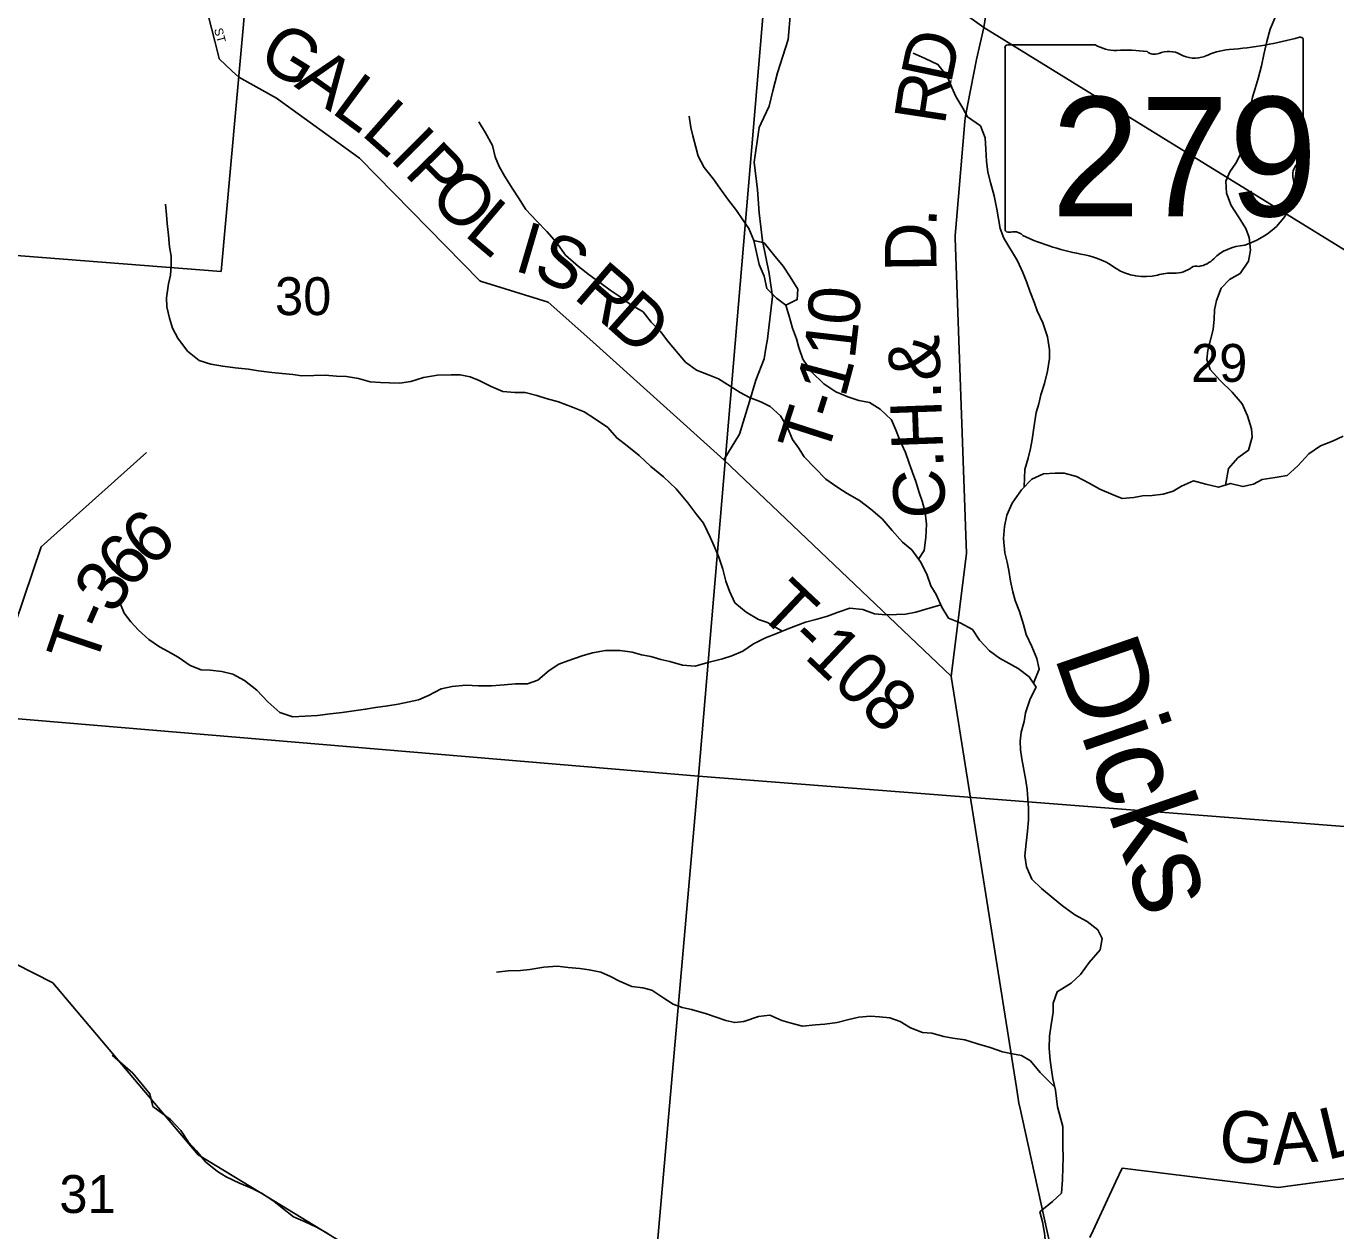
# Model space of a CAD drawing. Extents: x 1715311 to 2083412, y 146837 to 553079.
# Drawn here: x 1950183 to 1957824, y 317977 to 325005 of the extents above; entities that cross this region are included whole.
import ezdxf

# ---------------------------------------------------------------- set-up
doc = ezdxf.new("R2010")
doc.units = 0
for name, color, linetype in [('GM_X_City_Street', 7, 'Continuous'), ('GM_X_City_Street_Text', 7, 'Continuous'), ('GM_X_Corporation', 7, 'Continuous'), ('GM_X_County_Road', 7, 'Continuous'), ('GM_X_County_Road_Text', 7, 'Continuous'), ('GM_X_Minor_Lake', 7, 'Continuous'), ('GM_X_Minor_River', 7, 'Continuous'), ('GM_X_Minor_River_Text', 7, 'Continuous'), ('GM_X_Section', 7, 'Continuous'), ('GM_X_Section_Text', 7, 'Continuous'), ('GM_X_State_Location', 7, 'Continuous'), ('GM_X_State_Route', 7, 'Continuous'), ('GM_X_State_Shield', 7, 'Continuous'), ('GM_X_Township_Road', 7, 'Continuous'), ('GM_X_Township_Road_Text', 7, 'Continuous'), ('GM_X_Township_ROW', 7, 'Continuous')]:
    doc.layers.add(name, color=color, linetype=linetype)

msp = doc.modelspace()

# ---------------------------------------------------------------- linework, layer by layer
at = {"layer": 'GM_X_City_Street'}
msp.add_lwpolyline([(1951423.1, 324707.2), (1951385.1, 324743.2), (1951309.1, 324815.3), (1951309, 324815.4), (1951283.4, 324916.9), (1951245.1, 325069.3), (1951245.1, 325069.4)], dxfattribs=at)
at = {"layer": 'GM_X_Corporation'}
msp.add_lwpolyline([(1951553, 326137.7), (1951320.1, 323573.7), (1948435.1, 323799.8), (1948400, 323332.9), (1945758.3, 323632.3), (1946231.5, 329032.2)], dxfattribs=at)
at = {"layer": 'GM_X_County_Road'}
for points in [[(1955769.4, 324997.5), (1955798.2, 325171.4), (1955929.3, 325842), (1956302.2, 327750.6), (1956335.4, 327888.1)], [(1956223.5, 317578.5), (1956214.1, 317630.7), (1956206.7, 317671.7), (1956192.9, 317733.6), (1955977.5, 318708.8), (1955977.1, 318709.8), (1955960.8, 318812.4), (1955581.8, 321199.9), (1955579.4, 321213.7), (1955590.7, 321304.2), (1955668.8, 321930), (1955668.8, 321930.8), (1955665.1, 322035), (1955603.4, 323768.3), (1955602.7, 323782.8), (1955610.4, 323873), (1955659.2, 324449.1), (1955660.8, 324468.2), (1955677.3, 324552.4), (1955727.7, 324810.4), (1955769.4, 324997.5)]]:
    msp.add_lwpolyline(points, dxfattribs=at)
at = {"layer": 'GM_X_Minor_Lake'}
for points in [[(1954428.4, 323754.4), (1954459.7, 323614.2), (1954489.3, 323546), (1954505, 323473.8), (1954560.6, 323417.6), (1954614.3, 323377.3)], [(1954614.3, 323377.3), (1954682.1, 323410.1), (1954686, 323470.1), (1954640.1, 323542.2), (1954600.2, 323604.2), (1954542.4, 323672.2), (1954488.5, 323740.2), (1954428.4, 323754.4)]]:
    msp.add_lwpolyline(points, dxfattribs=at)
at = {"layer": 'GM_X_Minor_River'}
for points in [[(1957179.3, 322327.4), (1957198.3, 322425.1), (1957252.5, 322486.9), (1957314.5, 322530.6), (1957336.8, 322606.6), (1957331, 322656.6), (1957309.4, 322730.8), (1957277.8, 322801), (1957218.2, 322869.3), (1957148.7, 322937.7), (1957091.1, 323002), (1957071.4, 323060.1), (1957077.6, 323114.1), (1957091.8, 323174.1), (1957108.1, 323236.1), (1957114.3, 323296.1), (1957116.5, 323350.1), (1957126.8, 323404.1), (1957155, 323476), (1957203.1, 323527.9), (1957265.1, 323561.6), (1957315.3, 323633.4), (1957325.6, 323697.4), (1957317.9, 323771.5), (1957298.2, 323823.6), (1957256.6, 323891.9), (1957213, 323958.1), (1957185.3, 324030.3), (1957181.7, 324100.4), (1957205.8, 324154.3), (1957240, 324206.2), (1957274.2, 324270.1), (1957284.4, 324338.1), (1957300.8, 324418.1), (1957313, 324480.1), (1957325.2, 324536), (1957337.4, 324590), (1957353.6, 324642), (1957371.8, 324700), (1957390.1, 324773.9), (1957404.4, 324839.9), (1957420.7, 324915.9), (1957440.9, 324987.9), (1957473.2, 325065.8)], [(1956006.5, 322316.8), (1956009, 322418.4), (1956029.2, 322484.3), (1956043.4, 322540.3), (1956051.6, 322594.3), (1956061.9, 322662.3), (1956076.3, 322750.3), (1956090.5, 322802.3), (1956102.7, 322854.3), (1956124.9, 322920.2), (1956141.2, 322992.2), (1956153.5, 323066.2), (1956153.7, 323116.3), (1956142, 323192.4), (1956114.4, 323274.5), (1956080.8, 323344.8), (1956063.1, 323394.9), (1956039.4, 323459), (1956021.7, 323509.1), (1955998, 323567.3), (1955966.4, 323635.5), (1955887.1, 323767.9), (1955865.4, 323824.1), (1955855.7, 323880.1), (1955845.9, 323938.2), (1955830.3, 324014.4), (1955808.7, 324092.5), (1955793, 324152.6), (1955785.3, 324216.7), (1955781.6, 324286.8), (1955777.9, 324352.8), (1955750.3, 324423), (1955674.7, 324475.4), (1955646.9, 324525.6), (1955607.3, 324593.8), (1955583.6, 324647.9), (1955556, 324714.1), (1955502.4, 324780.4), (1955428.7, 324816.7), (1955359, 324847.1)], [(1952904.3, 324309.5), (1952862.7, 324381.7), (1952825.1, 324445.9)], [(1955388.8, 321896.1), (1955422.3, 321946.6), (1955432.6, 322022.7), (1955434.9, 322098.7), (1955427.2, 322168.8), (1955411.5, 322232.9), (1955393.8, 322285), (1955374.1, 322349.2), (1955354.4, 322401.3), (1955332.7, 322461.4), (1955313, 322517.6), (1955279.4, 322589.8), (1955255.7, 322653.9), (1955232, 322708.1), (1955166.4, 322770.4), (1955102.7, 322808.7), (1955040.9, 322821), (1954977.2, 322843.3), (1954907.4, 322871.6), (1954837.8, 322918), (1954764.3, 322988.3), (1954714.7, 323062.6), (1954691.1, 323130.8), (1954677.3, 323180.9), (1954653.6, 323243), (1954634, 323313.2), (1954614.3, 323377.3), (1954560.6, 323417.6), (1954505, 323473.8), (1954489.3, 323546), (1954459.7, 323614.2), (1954428.4, 323754.4), (1954398.7, 323824.6), (1954365, 323874.8), (1954327.3, 323929), (1954275.8, 323997.2), (1954230.1, 324059.5), (1954192.5, 324111.7), (1954138.9, 324180), (1954103.2, 324246.2), (1954089.5, 324298.3), (1954071.8, 324364.4), (1954060.1, 324414.5), (1954050.4, 324480.6)], [(1956200.5, 318700.1), (1956188.9, 318796.9), (1956173.2, 318863), (1956165.4, 318917.1), (1956157.7, 318973.1), (1956152, 319041.2), (1956154.3, 319113.3), (1956162.6, 319179.3), (1956174.9, 319253.3), (1956175.1, 319305.3), (1956197.3, 319371.3), (1956279.4, 319420.9), (1956333.5, 319472.7), (1956385.6, 319542.6), (1956449.8, 319616.3), (1956460.1, 319682.3), (1956436.4, 319732.5), (1956372.7, 319780.8), (1956301.1, 319821.1), (1956229.4, 319873.5), (1956175.7, 319917.8), (1956106.1, 319974.1), (1956050.5, 320028.4), (1956018.9, 320100.6), (1956009.2, 320164.7), (1956017.5, 320238.7), (1956025.8, 320308.7), (1956030.1, 320374.8), (1956030.4, 320444.8), (1956026.6, 320496.9), (1956022.8, 320550.9), (1956015.1, 320605), (1956001.4, 320677.1), (1955991.7, 320731.2), (1955983.9, 320783.3), (1955982.2, 320833.3), (1955988.4, 320885.3), (1956006.6, 320949.3), (1956012.8, 320999.3), (1956041.1, 321081.2), (1956075.3, 321149.1), (1956035.7, 321209.4), (1955970, 321257.7), (1955918.3, 321286), (1955862.5, 321318.2), (1955802.9, 321360.5), (1955745.2, 321422.8), (1955703.6, 321485.1), (1955631.9, 321523.4), (1955564.2, 321551.7), (1955524.6, 321616), (1955493, 321690.1), (1955461.3, 321740.3), (1955437.6, 321808.5), (1955400, 321880.7), (1955350.4, 321949), (1955296.7, 321995.2), (1955235.2, 322063.6), (1955177.6, 322129.9), (1955112, 322186.2), (1955044.4, 322238.6), (1954972.7, 322278.9), (1954919, 322313.2), (1954849.3, 322361.5), (1954783.8, 322427.8), (1954722.2, 322492.2), (1954688.5, 322544.4), (1954654.8, 322594.5), (1954625.2, 322662.7), (1954583.6, 322731), (1954523.9, 322785.3), (1954470.2, 322813.5), (1954402.4, 322837.8), (1954348.7, 322868.1), (1954275.1, 322914.5), (1954223.3, 322946.7), (1954163.6, 322971), (1954093.8, 322997.3), (1954030.2, 323045.6), (1953986.5, 323095.8), (1953925, 323168.2), (1953885.3, 323222.4), (1953829.7, 323278.7), (1953782, 323338.9), (1953708.4, 323381.3), (1953642.8, 323429.6), (1953591, 323463.9), (1953537.3, 323504.1), (1953467.7, 323554.5), (1953406.1, 323602.8), (1953330.5, 323669.1), (1953277, 323743.4), (1953221.4, 323807.7), (1953159.8, 323870), (1953098.2, 323936.3), (1953054.6, 324002.6), (1953022.9, 324054.8), (1952975.3, 324127), (1952943.7, 324187.2), (1952920, 324243.3), (1952904.3, 324309.5)], [(1954593.8, 321476), (1954508.5, 321526.4), (1954456.7, 321542.6), (1954383.1, 321587), (1954317.4, 321641.3), (1954285.8, 321709.5), (1954266.1, 321767.6), (1954248.4, 321837.8), (1954224.8, 321907.9), (1954197.1, 321972.1), (1954173.4, 322024.2), (1954133.9, 322104.5), (1954096.2, 322154.7), (1954042.6, 322225), (1953975.1, 322305.3), (1953901.6, 322375.7), (1953828, 322436.1), (1953760.5, 322500.4), (1953688.9, 322556.8), (1953629.2, 322603), (1953577.6, 322663.3), (1953498, 322715.7), (1953438.3, 322754), (1953370.6, 322782.3), (1953288.9, 322812.7), (1953217.2, 322833), (1953163.4, 322849.3), (1953093.6, 322867.6), (1953033.7, 322867.8), (1952963.9, 322874.2), (1952896.2, 322902.5), (1952826.5, 322936.8), (1952772.7, 322959), (1952714.9, 322971.3), (1952663.1, 322971.5), (1952583.2, 322967.9), (1952501.4, 322956.2), (1952427.4, 322932.5), (1952363.5, 322922.8), (1952303.7, 322925), (1952249.8, 322925.3), (1952190, 322929.5), (1952122.2, 322949.8), (1952052.4, 322960.2), (1951994.6, 322962.4), (1951926.8, 322968.7), (1951860.9, 322967), (1951791.1, 322965.3), (1951739.3, 322973.5), (1951677.4, 322977.8), (1951615.6, 322984), (1951537.8, 322994.4), (1951480, 323004.6), (1951402.2, 323011), (1951330.4, 323021.3), (1951260.6, 323033.6), (1951192.9, 323053.9), (1951125.3, 323108.2), (1951067.8, 323184.5), (1951036.1, 323242.7), (1951020.4, 323300.8), (1951004.7, 323367), (1951002.9, 323421), (1951013.3, 323501), (1951025.5, 323553), (1951029.7, 323611), (1951029.9, 323663.1), (1951020.2, 323717.1), (1951014.5, 323785.2), (1951006.8, 323853.3), (1951001, 323903.4), (1950995.3, 323967.4)], [(1956060.6, 321171.5), (1956093.7, 321253.1), (1956080, 321315.2), (1956050.4, 321385.4), (1956016.8, 321455.6), (1956001.1, 321513.8), (1955977.5, 321589.9), (1955953.8, 321654.1), (1955940, 321704.2), (1955926.3, 321766.3), (1955916.6, 321828.4), (1955906.9, 321878.5), (1955893.1, 321932.5), (1955885.5, 322016.6), (1955891.8, 322086.7), (1955904.1, 322152.7), (1955936.3, 322222.6), (1955990.5, 322300.4), (1956050.6, 322362.2), (1956118.6, 322393.9), (1956186.5, 322397.6), (1956238.4, 322397.3), (1956310.1, 322377), (1956385.8, 322338.6), (1956447.5, 322304.3), (1956525.2, 322270), (1956577, 322249.7), (1956644.8, 322255.4), (1956696.8, 322265.2), (1956752.7, 322266.9), (1956816.5, 322274.7), (1956874.5, 322292.4), (1956924.5, 322322.2), (1956994.5, 322351.9), (1957066.2, 322333.6), (1957140, 322315.2), (1957209.9, 322336.9), (1957281.7, 322318.6), (1957343.6, 322332.3), (1957393.6, 322360.1), (1957469.5, 322371.8), (1957539.4, 322383.5), (1957601.5, 322439.2), (1957665.7, 322509), (1957733.7, 322556.7), (1957803.7, 322584.5), (1957867.7, 322612.2)], [(1955519.4, 321628.1), (1955426.7, 321602.4), (1955372.8, 321586.6), (1955312.9, 321574.9), (1955261, 321573.1), (1955199.1, 321571.4), (1955133.3, 321575.7), (1955063.6, 321602), (1954987.8, 321610.3), (1954919.8, 321586.6), (1954857.9, 321562.9), (1954789.9, 321543.2), (1954730, 321527.4), (1954674, 321505.7), (1954622.1, 321487.9), (1954556.1, 321460.1), (1954496.1, 321436.4), (1954426.1, 321400.7), (1954364.1, 321358.9), (1954300.1, 321331.2), (1954246.2, 321313.4), (1954160.3, 321291.8), (1954086.4, 321272.1), (1954012.6, 321276.4), (1953938.8, 321298.7), (1953885, 321311), (1953827.2, 321327.2), (1953773.4, 321337.5), (1953719.6, 321353.7), (1953647.8, 321362.1), (1953564, 321362.4), (1953488.1, 321348.8), (1953426.1, 321331), (1953344.2, 321301.3), (1953290.3, 321283.6), (1953234.2, 321245.8), (1953168.1, 321190), (1953108.2, 321168.3), (1953038.3, 321168.6), (1952972.5, 321162.9), (1952898.6, 321157.2), (1952822.8, 321155.5), (1952749, 321159.8), (1952669.1, 321152.2), (1952605.2, 321138.4), (1952531.2, 321100.7), (1952471.3, 321075), (1952417.3, 321063.2), (1952353.4, 321049.5), (1952293.5, 321039.7), (1952221.7, 321030), (1952163.8, 321020.2), (1952081.9, 321008.6), (1952026, 321000.8), (1951956.1, 320993.1), (1951882.3, 320983.4), (1951738.6, 320976), (1951662.9, 321000.4), (1951593.3, 321062.7), (1951529.7, 321131), (1951456.2, 321187.4), (1951388.5, 321223.7), (1951324.7, 321240), (1951256.9, 321248.3), (1951205, 321250.5), (1951139.3, 321274.8), (1951069.7, 321323.1), (1951012, 321357.4), (1950960.2, 321383.7), (1950898.5, 321426), (1950838.9, 321480.3), (1950793.2, 321530.5), (1950755.6, 321580.7), (1950733.8, 321632.8)], [(1956184.6, 318814.7), (1956099.5, 318901.4), (1956041.9, 318967.7), (1955990.2, 318999.9), (1955938.3, 319010.2), (1955878.5, 319020.4), (1955806.8, 319046.8), (1955733.1, 319067.1), (1955659.3, 319091.5), (1955589.5, 319101.8), (1955537.7, 319110), (1955467.9, 319130.3), (1955412.1, 319134.6), (1955342.3, 319160.9), (1955282.6, 319197.2), (1955222.9, 319219.5), (1955161, 319225.8), (1955109.2, 319230), (1955041.3, 319224.3), (1954983.4, 319210.6), (1954915.5, 319192.9), (1954843.6, 319183.2), (1954787.7, 319179.4), (1954711.8, 319171.7), (1954646, 319188), (1954592.2, 319204.3), (1954522.5, 319234.6), (1954456.6, 319226.9), (1954370.7, 319197.3), (1954316.8, 319191.5), (1954265, 319203.7), (1954151.4, 319242.3), (1954065.7, 319268.7), (1954009.9, 319278.9), (1953958.1, 319299.2), (1953904.4, 319333.4), (1953832.7, 319381.8), (1953780.9, 319394), (1953717.1, 319402.3), (1953645.4, 319432.6), (1953591.7, 319460.9), (1953535.9, 319485.2), (1953468.1, 319499.5), (1953414.3, 319507.7), (1953344.4, 319514), (1953282.6, 319520.3), (1953202.8, 319514.6), (1953120.9, 319501), (1953067, 319495.2), (1952995.2, 319493.5), (1952927.3, 319485.8)], [(1950922.8, 318703.1), (1950905, 318776), (1950859.4, 318830.2), (1950805.8, 318896.5), (1950746.2, 318948.8), (1950684.5, 319001.1)], [(1951942.9, 317961.1), (1951876.8, 317999.1), (1951810.8, 318029.1), (1951742.7, 318059), (1951678.6, 318109.1), (1951628.6, 318149.1), (1951556.5, 318197.1), (1951502.5, 318223.1), (1951428.4, 318255.1), (1951350.3, 318291.1), (1951300.3, 318323.1), (1951230.2, 318379.1), (1951176.1, 318443.2), (1951130.1, 318493.2), (1951086, 318561.3), (1951025.9, 318625.4), (1950922.8, 318703.1)], [(1956138, 317838.2), (1956132, 317890.3), (1956123.9, 317962.4), (1956111.9, 318028.5), (1956097.8, 318088.6), (1956171.9, 318148.8), (1956223.9, 318196.9), (1956229.9, 318275.1), (1956231.8, 318349.2), (1956233.8, 318403.3), (1956231.7, 318471.4), (1956231.7, 318585.6), (1956200.5, 318700.1)]]:
    msp.add_lwpolyline(points, dxfattribs=at)
at = {"layer": 'GM_X_Section'}
for points in [[(1948672.9, 326443.5), (1954563.6, 326023.5), (1954105.8, 320629), (1948197.3, 321127.1), (1948406.9, 323469.3)], [(1954563.6, 326023.5), (1960176.2, 325575.7), (1959744.5, 320189.1), (1954105.8, 320629)], [(1948197.3, 321127.1), (1954105.8, 320629), (1953643.2, 315366.5), (1947726.7, 315880.4), (1947914.1, 318010.6)], [(1954105.8, 320629), (1959744.5, 320189.1), (1959289.9, 314876.8), (1954509.4, 315291.9), (1953643.2, 315366.5)]]:
    msp.add_lwpolyline(points, close=True, dxfattribs=at)
at = {"layer": 'GM_X_State_Route'}
for points in [[(1952758, 326079.9), (1952855.9, 326058), (1953116, 325883.6), (1954496.8, 325911.9), (1955769.4, 324997.5), (1958874.9, 323084.4), (1959307.8, 322840.8), (1960540.6, 322714.5), (1961879.5, 321752.1), (1962403.9, 321517.6), (1963838.9, 321035.1), (1963965.3, 320991.3), (1964281.5, 320971.3), (1965388.2, 320901.5), (1965711.6, 320881), (1966211.2, 320756.8), (1966668.3, 320492.4), (1967805.6, 319697)], [(1947802.3, 323798.6), (1947787.6, 323677.7), (1947774.5, 323530.8), (1947849.5, 323393.2), (1948159.9, 323005.8), (1948297.9, 322811.6), (1948399.5, 322673.9), (1948482, 322522.6), (1948874.1, 321299.1), (1949047.1, 320993.4), (1949062.5, 320966.1), (1949178.1, 320772.9), (1949480.2, 320464.3), (1949778.4, 319708.5), (1950338.7, 319424.1), (1951187, 318419.9), (1951547.6, 318200.1), (1952061.5, 317886.8)]]:
    msp.add_lwpolyline(points, dxfattribs=at)
at = {"layer": 'GM_X_State_Shield'}
for p, q in [((1955893.9, 324878.3), (1955893.9, 323821.7)), ((1956420.6, 324896.5), (1955911, 324896.5)), ((1957634.1, 324370), (1957634.1, 324922.7)), ((1957633.9, 324370.1), (1957634.1, 324370))]:
    msp.add_line(p, q, dxfattribs=at)
for centre, major_axis, start_param, end_param in [((1955913.8, 324880.6), (20.2, 0), 1.712693, 3.28349), ((1956542, 325019.2), (195.5, 0), 4.042523, 4.731795), ((1957014.2, 326337.1), (1845.5, 0), 4.814394, 5.042369), ((1957614.8, 324925), (19.4, 0), 6.141152, 7.989035), ((1956606.8, 324303.3), (702, 0), 1.404758, 1.657858), ((1956766.2, 324886.1), (56.4, 0), 3.836095, 5.185415), ((1956849, 324763.9), (117.3, 0), 0.950623, 2.079405), ((1957000.4, 324931.4), (141.1, 0), 4.081561, 5.145723), ((1957249.6, 324573.8), (371.3, 0), 1.699011, 2.107814), ((1957629.6, 324329.4), (30, 0), 1.883978, 3.671073), ((1957613.4, 324367.8), (20.7, 0), 5.05454, 6.418171), ((1957438.8, 324259.5), (180, 0), 5.934695, 6.695948), ((1957703.5, 324138.6), (130.9, 0), 2.387724, 3.262537), ((1957117.6, 324068.3), (461.6, 0), 5.101752, 6.440018), ((1955914, 323819.4), (20.3, 0), 3.00124, 4.508301), ((1955917.1, 323927.5), (155.2, 0), 4.665946, 4.897461), ((1955948.8, 323760.7), (56, 0), 0.519207, 1.627899), ((1956655.4, 324710.1), (1332.7, 0), 4.195997, 4.488961), ((1957312.2, 323525.1), (252.8, 0), 1.647645, 2.488434), ((1956258.1, 323347), (417, 0), 0.823519, 1.323587), ((1956709.1, 323755.5), (264.6, 0), 4.026481, 4.996735), ((1956881.3, 323676.4), (141, 0), 4.691044, 5.507374), ((1957008.8, 323574), (39.7, 0), 1.147584, 2.315152), ((1956991.9, 323719.3), (149.1, 0), 4.937069, 5.64225), ((1956861.9, 323390.2), (217.4, 0), 1.495662, 1.94098)]:
    msp.add_ellipse(centre, major_axis=major_axis, ratio=0.8, start_param=start_param, end_param=end_param, dxfattribs=at)
at = {"layer": 'GM_X_Township_Road'}
for points in [[(1952836.8, 323516.1), (1952829.2, 323518.5), (1952128.9, 324234.4), (1951643.2, 324584.6), (1951423.1, 324707.2)], [(1954540.1, 324628.3), (1954517.5, 324537.6), (1954471.6, 324438.2), (1954460.1, 324413.3), (1954431.4, 324212.4), (1954450.6, 324049.8), (1954460.1, 323915.9), (1954479.2, 323753.2), (1954517.5, 323561.9), (1954536.6, 323428), (1954509.9, 323196.5)], [(1955579.4, 321213.7), (1954253.2, 322475.2), (1953471.9, 323179.2), (1953228, 323394), (1952839, 323515.4), (1952836.8, 323516.1)], [(1954509.9, 323196.5), (1954507.9, 323179.3), (1954499, 323125.7), (1954488.8, 323064.5), (1954441, 322940.1), (1954402.7, 322815.8), (1954345.3, 322624.4), (1954253.2, 322475.2)], [(1949047.1, 320993.4), (1949611.1, 320942.3), (1950014.3, 321212.9), (1950271.6, 321966.9), (1950884.6, 322518.1)], [(1957875.9, 318282.1), (1957790.4, 318270.6), (1957531, 318235.6), (1957489.2, 318229.9), (1957427, 318237.5), (1956595.5, 318340.1), (1956577.4, 318342.3), (1956540.8, 318263.9), (1956407.9, 317979.2), (1956389, 317938.8)]]:
    msp.add_lwpolyline(points, dxfattribs=at)
at = {"layer": 'GM_X_Township_ROW'}
msp.add_lwpolyline([(1954496.8, 325911.9), (1954628.6, 325661.8), (1954641.8, 325086.9), (1954628.5, 324926.8), (1954566.3, 324733.6), (1954540.1, 324628.3)], dxfattribs=at)

# ---------------------------------------------------------------- texts
at = {"layer": 'GM_X_City_Street_Text'}
msp.add_text('ST', height=50, rotation=284.93778, dxfattribs=at).set_placement((1951278.9, 324986.7))
at = {"layer": 'GM_X_County_Road_Text'}
for s, rotation, p in [('D', 78.12353, (1955578.2, 324661.6)), ('R', 81.3847, (1955542.1, 324422.4)), ('.', 86.02115, (1955491.4, 323830.6)), ('D', 90.69218, (1955494.8, 323573.1)), ('C.H.&', 92.06368, (1955547.4, 322137.7))]:
    msp.add_text(s, height=300, rotation=rotation, dxfattribs=at).set_placement(p)
at = {"layer": 'GM_X_Minor_River_Text'}
msp.add_text('Dicks', height=500.04, rotation=288.99826, dxfattribs=at).set_placement((1956177.4, 321335.4))
at = {"layer": 'GM_X_Section_Text'}
for s, p in [('30', (1951635, 323319.2)), ('29', (1956978.8, 322929.8)), ('31', (1950376.6, 318081))]:
    msp.add_text(s, height=221, rotation=0.00001, dxfattribs=at).set_placement(p)
at = {"layer": 'GM_X_State_Location'}
for s in ['s', 'r']:
    msp.add_text(s, height=1, dxfattribs=at).set_placement((1956744.4, 324279.8))
msp.add_text('279', height=1, rotation=0.00001, dxfattribs=at).set_placement((1956391.4, 324207))
at = {"layer": 'GM_X_State_Shield'}
msp.add_text('279', height=696.1, dxfattribs=at).set_placement((1956163.8, 323896.2))
at = {"layer": 'GM_X_Township_Road_Text'}
for s, rotation, p in [('G', 328.23905, (1951521.4, 324792.4)), ('A', 324.80237, (1951741.8, 324656.1)), ('L', 323.51324, (1951956.1, 324504.9)), ('L', 318.48107, (1952131.1, 324375.9)), ('I', 315.16007, (1952295.8, 324230.3)), ('P', 314.3213, (1952382.4, 324144.2)), ('O', 314.36973, (1952524, 323999.2)), ('L', 319.88009, (1952731.7, 323789.1)), ('I', 343.58487, (1953021.8, 323580.8)), ('S', 335.02674, (1953128.9, 323550.1)), ('R', 319.22345, (1953369.4, 323423.1)), ('D', 318.36344, (1953555.1, 323262.9)), ('0', 85.96893, (1955039.5, 323254.1)), ('1', 83.41072, (1955017, 323056)), ('1', 75.05324, (1954960.4, 322830.6)), ('-', 72.44335, (1954919.1, 322698.8)), ('T', 72.13156, (1954849.7, 322483.5)), ('6', 42.02019, (1950908.5, 321839.4)), ('6', 46.92173, (1950787.1, 321709.2)), ('3', 56.72479, (1950694.1, 321565.3)), ('T-108', 316.59104, (1954440.8, 321583.2)), ('-', 66.52786, (1950651.5, 321464.2)), ('T', 71.4294, (1950582.4, 321257.9)), ('G', 352.66534, (1957128.2, 318395.8)), ('L', 13.4921, (1957771.5, 318388.8)), ('A', 4.41506, (1957457.1, 318360.4))]:
    msp.add_text(s, height=300, rotation=rotation, dxfattribs=at).set_placement(p)

doc.saveas('drawing.dxf')
